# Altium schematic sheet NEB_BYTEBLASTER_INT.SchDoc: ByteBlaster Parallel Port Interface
size A4; CompanyName: Altium; DrawnBy: Ch.W.; Organization: Altium Limited; Address1: L3, 12a Rodborough Rd; Address2: Frenchs Forest; Address3: NSW; Address4: Australia 2086; DocumentNumber: 5; Revision: V0.9; SheetNumber: 5; SheetTotal: 10
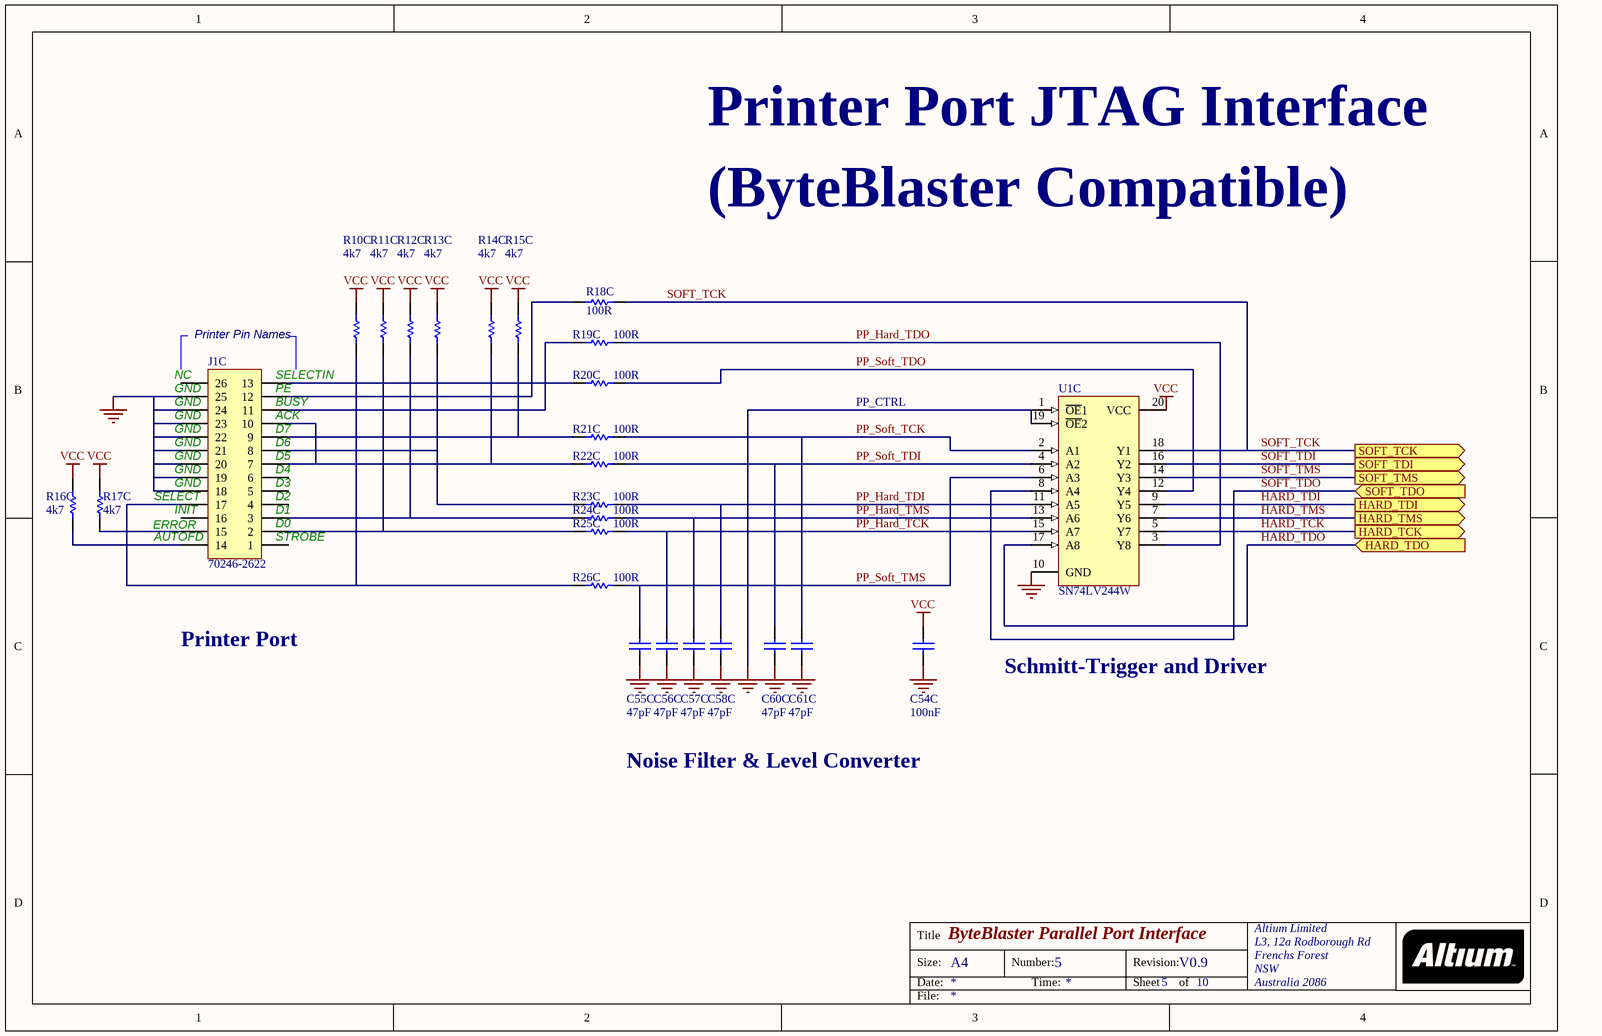
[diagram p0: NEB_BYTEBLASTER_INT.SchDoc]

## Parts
C54C  100nF  [CC2012-0805]
C55C  47pF  [CC2012-0805]
C56C  47pF  [CC2012-0805]
C57C  47pF  [CC2012-0805]
C58C  47pF  [CC2012-0805]
C60C  47pF  [CC2012-0805]
C61C  47pF  [CC2012-0805]
J1C  70246-2622  [HDR2X13_CEN_LP]
R10C  4k7  [CC2012-0805]
R11C  4k7  [CR2012-0805]
R12C  4k7  [CR2012-0805]
R13C  4k7  [CR2012-0805]
R14C  4k7  [CR2012-0805]
R15C  4k7  [CR2012-0805]
R16C  4k7  [CR2012-0805]
R17C  4k7  [CR2012-0805]
R18C  100R  [CC2012-0805]
R19C  100R  [CR2012-0805]
R20C  100R  [CR2012-0805]
R21C  100R  [CR2012-0805]
R22C  100R  [CR2012-0805]
R23C  100R  [CR2012-0805]
R24C  100R  [CR2012-0805]
R25C  100R  [CR2012-0805]
R26C  100R  [CR2012-0805]
U1C  SN74LV244W  [SSO-G20/P.65]

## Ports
HARD_TCK (out), HARD_TDI (out), HARD_TDO (in), HARD_TMS (out), SOFT_TCK (out), SOFT_TDI (out), SOFT_TDO (in), SOFT_TMS (out)

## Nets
GND: C54C.2 C55C.2 C56C.2 C57C.2 C58C.2 C60C.2 C61C.2 J1C.18 J1C.19 J1C.20 J1C.21 J1C.22 J1C.23 J1C.24 J1C.25 U1C.1(~{OE}1) U1C.10(GND) U1C.19(~{OE}2)
VCC: C54C.1 R10C.1 R11C.1 R12C.1 R13C.1 R14C.1 R15C.1 R16C.1 R17C.1 U1C.20(VCC)
HARD_TCK: U1C.5(Y7) ; port HARD_TCK
HARD_TDI: U1C.9(Y5) ; port HARD_TDI
HARD_TDO: U1C.17(A8) ; port HARD_TDO
HARD_TMS: U1C.7(Y6) ; port HARD_TMS
PP_Hard_TCK: C56C.1 R25C.1 U1C.15(A7)
PP_Hard_TDI: C58C.1 R23C.1 U1C.11(A5)
PP_Hard_TDO: R19C.1 U1C.3(Y8)
PP_Hard_TMS: C57C.1 R24C.1 U1C.13(A6)
PP_Soft_TCK: C61C.1 R21C.1 U1C.2(A1)
PP_Soft_TDI: C60C.1 R22C.1 U1C.4(A2)
PP_Soft_TDO: R20C.1 U1C.12(Y4)
PP_Soft_TMS: C55C.1 R26C.1 U1C.6(A3)
SOFT_TCK: R18C.2 U1C.18(Y1) ; port SOFT_TCK
SOFT_TDI: U1C.16(Y2) ; port SOFT_TDI
SOFT_TDO: U1C.8(A4) ; port SOFT_TDO
SOFT_TMS: U1C.14(Y3) ; port SOFT_TMS
NetJ1C_2: J1C.2 R11C.2 R25C.2
NetJ1C_3: J1C.3 R12C.2 R24C.2
NetJ1C_7: J1C.7 J1C.10 R14C.2 R22C.2
NetJ1C_8: J1C.8 R13C.2 R23C.2
NetJ1C_9: J1C.9 R15C.2 R21C.2
NetJ1C_11: J1C.11 R19C.2
NetJ1C_12: J1C.12 R18C.1
NetJ1C_13: J1C.13 R20C.2
NetJ1C_14: J1C.14 R16C.2
NetJ1C_15: J1C.15 R17C.2
NetJ1C_17: J1C.17 R10C.2 R26C.2

Not connected (* = marked no-connect by the designer): J1C 1 4 5 6 16 26

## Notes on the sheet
- Printer Port JTAG Interface
- (ByteBlaster Compatible)
- (near J1C) NC
- Printer Pin Names
- (near J1C) SELECTIN
- (near J1C) GND
- (near J1C) PE
- (near J1C) BUSY
- (near J1C) ACK
- (near J1C) D6
- (near J1C) D7
- PP_CTRL
- (near J1C) SELECT
- (near J1C) INIT
- (near J1C) D1
- (near J1C) D2
- (near J1C) D3
- (near J1C) D4
- (near J1C) D5
- (near J1C) ERROR
- (near J1C) AUTOFD
- (near J1C) STROBE
- (near J1C) D0
- Printer Port
- Schmitt-Trigger and Driver
- Noise Filter & Level Converter

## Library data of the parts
C54C C55C C56C C57C C58C C60C C61C = CAP: Capacitor; Fitted: True
J1C = Header 13X2A: Header, 13-Pin, Dual row; Manufacturer: Generic Components; Class I: Connector; Fitted: True
R10C R11C R12C R13C R14C R15C R16C R17C R19C R20C R21C R22C R23C R24C R25C R26C = RES: Resistor; Fitted: True
R18C = RES: Resistor
U1C = SN54LV244W: Octal Buffer/Driver with 3-State Outputs; Package Information: Latest Revision: Jan-1995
